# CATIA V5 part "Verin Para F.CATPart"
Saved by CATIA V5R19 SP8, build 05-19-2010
Part number: Verin Para F
Bounding box of the stored display mesh (mm): x -44.968 to 44.968, y 97.104 to 490, z -630.961 to -401.211
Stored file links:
  G:\EU_thinkMotion\CFAO_2010\MMS_groupe3\MMS_groupe3\rdalborgo\rdalborgo\Verin Para F.CATPart
  G:\EU_thinkMotion\CFAO_2010\MMS_groupe3\MMS_groupe3\rdalborgo\rdalborgo\rdalborgo.CATProduct
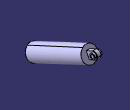
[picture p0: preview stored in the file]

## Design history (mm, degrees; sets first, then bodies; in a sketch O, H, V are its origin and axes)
Set1
  Plane1: linked copy from another document
  Point1 "A verin para": linked copy from another document
  Line1: linked copy from another document
  Point2: linked copy from another document
Body1 (main body)
  Sketch1 on Plane1, origin (0, 0, 0), H (0, 1, 0), V (0, 0, 1)
    circle A1 centre (470, -425) radius 10
    point P1 (470, -425)
    arc A2 centre (470, -425) radius 20 from (490, -425) to (461.538, -406.8783) ccw
    point P2 (470, -425)
    reference projected point E1 (470, -425) from Point1
    line L1 (425.2947, -423.8023) -> (442.2186, -460.0456)
    reference projected line E2 (-123.6389, -702.2015) -> (466.1687, -426.789) from Line1
    line L2 (442.2186, -460.0456) -> (478.462, -443.1217)
    point P5 (478.462, -443.1217)
    line L3 (425.2947, -423.8023) -> (461.538, -406.8783)
    point P6 (461.538, -406.8783)
    reference projected point E3 (470, -425) from Point1
    reference projected line E4 (-123.6389, -702.2015) -> (466.1687, -426.789) from Line1
    point P7 (490, -425)
    point P8 (490, -425)
    arc A3 centre (470, -425) radius 20 from (478.462, -443.1217) to (490, -425) ccw
    radius A1 = 10
    radius A2 = 20
    length L1 = 40
    distance L1 E3 = 40
    coincidence: P2 P1, E1 P2, P5 A2, P6 A2, P7 P8
    perpendicularity: L1 E2
    tangency: L2 A2, L3 A2
    parallelism: L3 E4
  Pad1: profile Sketch1, direction (1, 0, 0), length 10, mirrored extent
  Sketch2 on Plane1, origin (0, 0, 0), H (0, 1, 0), V (0, 0, 1)
    circle A1 centre (470, -425) radius 10
    point P1 (470, -425)
    circle A2 centre (470, -425) radius 15
    point P2 (470, -425)
    reference projected point E1 (470, -425) from Point1
    radius A1 = 10
    radius A2 = 15
    coincidence: P2 P1, P2 E1
  Pad2: profile Sketch2, direction (-1, 0, 0), length 20, mirrored extent
  Sketch3 on Plane1, origin (0, 0, 0), H (0, 1, 0), V (0, 0, 1)
    point P1 (433.7567, -441.9239)
    line L1 (433.7567, -441.9239) -> (414.7172, -401.1502)
    line L2 (414.7172, -401.1502) -> (97.076, -549.4737)
    line L3 (97.076, -549.4737) -> (111.8845, -581.1867)
    line L4 (111.8845, -581.1867) -> (120.9453, -576.9557)
    line L5 (120.9453, -576.9557) -> (110.3679, -554.3036)
    line L6 (110.3679, -554.3036) -> (409.8874, -414.442)
    line L7 (409.8874, -414.442) -> (424.6958, -446.1549)
    line L8 (424.6958, -446.1549) -> (433.7567, -441.9239)
    reference projected line E1 (-123.6389, -702.2015) -> (466.1687, -426.789) from Line1
    reference projected point E2 (470, -425) from Point1
    reference projected point E3 (116.1155, -590.2475) from Point2
    distance L1 L7 = 10
    distance L8 L2 = 45
    distance L6 L2 = 10
    distance L4 L2 = 35
    distance L3 L5 = 10
    distance P1 E2 = 40
    distance L3 E3 = 0
    perpendicularity: L2 L1
    parallelism: L3 L1
    coincidence: L8 E1
  Shaft1: profile Sketch3, axis Line1, angle 360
